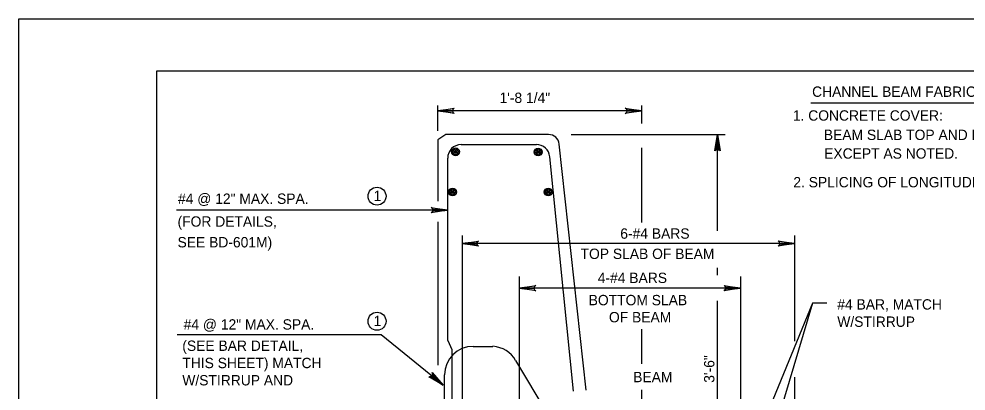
# Model space of a CAD drawing. Extents: x 642009 to 642864, y 298232 to 300014.
# Drawn here: x 642008.7 to 642283.1, y 299906 to 300013.8 of the extents above; entities that cross this region are included whole.
import ezdxf

# ---------------------------------------------------------------- set-up
doc = ezdxf.new("R2010")
doc.units = 0
for name, color, linetype in [('1', 7, 'Continuous'), ('2', 7, 'Continuous'), ('PLT-BNDY', 7, 'Continuous')]:
    doc.layers.add(name, color=color, linetype=linetype)

msp = doc.modelspace()

# ---------------------------------------------------------------- linework, layer by layer
at = {"layer": '1'}
for points in [[(642134.55, 299986.63), (642134.39, 299986.96), (642130.01, 299987.2), (642134.55, 299986.63), (642134.79, 299986.43), (642130.01, 299987.2), (642134.38, 299987.41), (642134.54, 299987.74), (642130.01, 299987.2), (642134.79, 299987.96), (642134.54, 299987.74)], [(642184.59, 299987.77), (642184.76, 299987.44), (642189.13, 299987.2), (642184.59, 299987.77), (642184.36, 299987.97), (642189.13, 299987.2), (642184.77, 299986.98), (642184.61, 299986.66), (642189.13, 299987.2), (642184.36, 299986.44), (642184.61, 299986.66)], [(642210.47, 299975.8), (642210.8, 299975.97), (642211.04, 299980.34), (642210.47, 299975.8), (642210.27, 299975.57), (642211.04, 299980.34), (642211.26, 299975.97), (642211.58, 299975.81), (642211.04, 299980.34), (642211.8, 299975.57), (642211.58, 299975.81)], [(642128.36, 299959), (642128.53, 299958.67), (642132.9, 299958.43), (642128.36, 299959), (642128.13, 299959.2), (642132.9, 299958.43), (642128.53, 299958.21), (642128.37, 299957.89), (642132.9, 299958.43), (642128.13, 299957.67), (642128.37, 299957.89)], [(642141.59, 299948.15), (642141.42, 299948.48), (642137.05, 299948.72), (642141.59, 299948.15), (642141.82, 299947.96), (642137.05, 299948.72), (642141.42, 299948.94), (642141.58, 299949.27), (642137.05, 299948.72), (642141.82, 299949.48), (642141.58, 299949.27)], [(642228.85, 299949.29), (642229.02, 299948.97), (642233.39, 299948.72), (642228.85, 299949.29), (642228.62, 299949.49), (642233.39, 299948.72), (642229.02, 299948.51), (642228.87, 299948.18), (642233.39, 299948.72), (642228.62, 299947.97), (642228.87, 299948.18)], [(642158.18, 299935.27), (642158.01, 299935.6), (642153.64, 299935.84), (642158.18, 299935.27), (642158.41, 299935.07), (642153.64, 299935.84), (642158.01, 299936.05), (642158.17, 299936.38), (642153.64, 299935.84), (642158.41, 299936.6), (642158.17, 299936.38)], [(642213.22, 299936.41), (642213.39, 299936.08), (642217.76, 299935.84), (642213.22, 299936.41), (642212.99, 299936.61), (642217.76, 299935.84), (642213.4, 299935.62), (642213.24, 299935.3), (642217.76, 299935.84), (642212.99, 299935.08), (642213.24, 299935.3)], [(642128.46, 299911.04), (642128.39, 299910.68), (642131.63, 299907.74), (642128.46, 299911.04), (642128.41, 299911.34), (642131.63, 299907.74), (642128.1, 299910.32), (642127.77, 299910.17), (642131.63, 299907.74), (642127.45, 299910.15), (642127.77, 299910.17)]]:
    msp.add_lwpolyline(points, dxfattribs=at)
for centre in [(642112.42, 299962.47), (642112.42, 299926.22)]:
    msp.add_circle(centre, 2.61, dxfattribs=at)
at = {"layer": '2'}
for p, q in [((642008.66, 300013.82), (642008.66, 300013.82)), ((642048.66, 299434.82), (642048.66, 299998.82)), ((642048.66, 299998.82), (642834.66, 299998.82)), ((642238.15, 299989.48), (642328.03, 299989.48)), ((642130.01, 299981.4), (642130.01, 299988.76)), ((642189.13, 299987.2), (642130.01, 299987.2)), ((642189.13, 299983.49), (642189.13, 299988.76)), ((642132.33, 299980.34), (642130.01, 299978.84)), ((642130.01, 299978.84), (642130.01, 299961)), ((642162.12, 299980.34), (642132.33, 299980.34)), ((642168.67, 299980.34), (642213.27, 299980.34)), ((642211.04, 299952.4), (642211.04, 299980.34)), ((642136.81, 299977.41), (642158.58, 299977.41)), ((642172.98, 299906.31), (642165.2, 299977.58)), ((642189.13, 299954.83), (642189.13, 299976.44)), ((642132.9, 299920.69), (642132.9, 299973.5)), ((642169.32, 299906.01), (642162.47, 299973.9)), ((642132.9, 299958.43), (642054.27, 299958.43)), ((642130.01, 299955.04), (642130.01, 299913.47)), ((642137.05, 299951.04), (642137.05, 299890.47)), ((642233.39, 299951.04), (642233.39, 299920.5)), ((642233.39, 299948.72), (642137.05, 299948.72)), ((642211.04, 299939.62), (642211.04, 299941.69)), ((642153.64, 299939.21), (642153.64, 299841.18)), ((642217.76, 299939.21), (642217.76, 299883.05)), ((642217.76, 299935.84), (642153.64, 299935.84)), ((642238.62, 299931.48), (642200.14, 299837.77)), ((642211.04, 299887.9), (642211.04, 299932.15)), ((642238.62, 299931.48), (642214.57, 299851.07)), ((642242.78, 299931.48), (642238.62, 299931.48)), ((642189.13, 299913.93), (642189.13, 299923.92)), ((642113.64, 299922.3), (642054.55, 299922.3)), ((642131.63, 299907.74), (642113.64, 299922.3)), ((642132.9, 299920.69), (642134.1, 299918.05)), ((642134.1, 299918.05), (642134.1, 299890.47)), ((642140.25, 299918.95), (642146, 299918.95)), ((642152.58, 299914.82), (642185.93, 299859.22)), ((642132, 299809.39), (642132, 299910.7)), ((642233.39, 299910.03), (642233.39, 299886.15)), ((642189.13, 299900.73), (642189.13, 299906.36))]:
    msp.add_line(p, q, dxfattribs=at)
for centre, radius in [((642135.17, 299975.33), 1.14), ((642135.17, 299975.33), 0.817), ((642135.17, 299975.33), 0.447), ((642135.17, 299975.33), 0.225), ((642135.17, 299975.33), 0.0966), ((642159.1, 299975.26), 1.14), ((642159.1, 299975.26), 0.817), ((642159.1, 299975.26), 0.447), ((642159.1, 299975.26), 0.225), ((642159.1, 299975.26), 0.0966), ((642134.3, 299963.67), 1.14), ((642134.3, 299963.67), 0.817), ((642162.02, 299963.67), 1.14), ((642162.02, 299963.67), 0.817), ((642134.3, 299963.67), 0.447), ((642134.3, 299963.67), 0.225), ((642134.3, 299963.67), 0.0966), ((642162.02, 299963.67), 0.447), ((642162.02, 299963.67), 0.225), ((642162.02, 299963.67), 0.0966)]:
    msp.add_circle(centre, radius, dxfattribs=at)
for centre, radius, start, end in [((642162.12, 299977.25), 3.09, 6.0211, 90), ((642136.81, 299973.5), 3.91, 90, 180), ((642158.58, 299973.5), 3.91, 5.8377, 90), ((642140.25, 299910.7), 8.25, 90, 180), ((642145.41, 299910.74), 8.25, 29.6571, 85.9214)]:
    msp.add_arc(centre, radius, start, end, dxfattribs=at)
at = {"layer": 'PLT-BNDY'}
msp.add_lwpolyline([(642008.66, 300013.82), (642849.66, 300013.82), (642849.66, 299419.82), (642008.66, 299419.82)], close=True, dxfattribs=at)

# ---------------------------------------------------------------- texts
at = {"layer": '2'}
for s, p in [('1\'-8 1/4"', (642147.91, 299989.47)), ('CHANNEL BEAM FABRICATION NOTES:', (642238.49, 299991.25)), ('1. CONCRETE COVER:', (642232.91, 299984.35)), ('BEAM SLAB TOP AND BOTTOM COVER 1 1/2", CHANNEL LEG COVER 2",', (642241.89, 299978.74)), ('EXCEPT AS NOTED.', (642241.99, 299973.34)), ('2. SPLICING OF LONGITUDINAL STEEL IS NOT ALLOWED.', (642233.05, 299965.03)), ('#4 @ 12" MAX. SPA.', (642054.76, 299960.24)), ('1', (642111.42, 299961.05)), ('(FOR DETAILS,', (642054.62, 299953.63)), ('SEE BD-601M)', (642054.62, 299947.63)), ('6-#4 BARS', (642182.91, 299950.14)), ('TOP SLAB OF BEAM', (642171.4, 299944.27)), ('4-#4 BARS', (642176.38, 299937.31)), ('BOTTOM SLAB', (642173.75, 299930.86)), ('#4 BAR, MATCH', (642245.79, 299929.61)), ('OF BEAM', (642179.63, 299925.91)), ('#4 @ 12" MAX. SPA.', (642056.39, 299923.81)), ('1', (642111.42, 299924.81)), ('W/STIRRUP', (642245.79, 299924.61)), ('(SEE BAR DETAIL, ', (642056, 299917.64)), ('THIS SHEET) MATCH', (642056, 299912.64)), ('W/STIRRUP AND', (642056, 299907.64)), ('  BEAM', (642184.42, 299908.56))]:
    msp.add_text(s, height=3, dxfattribs=at).set_placement(p)
msp.add_text('3\'-6"', height=3, rotation=90, dxfattribs=at).set_placement((642210.18, 299908.4))

doc.saveas('drawing.dxf')
